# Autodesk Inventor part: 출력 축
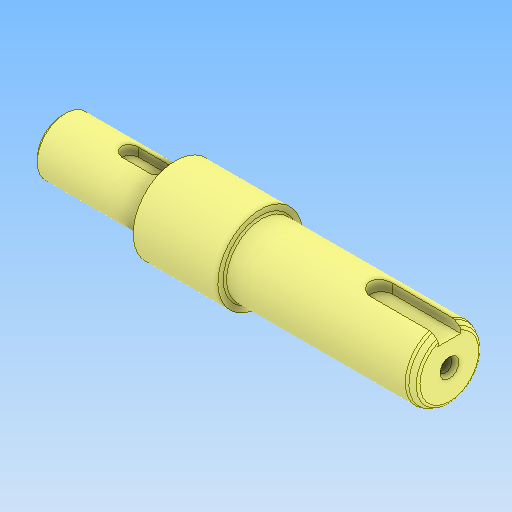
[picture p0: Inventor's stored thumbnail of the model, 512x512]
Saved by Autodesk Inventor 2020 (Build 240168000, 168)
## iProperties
Created: 2025-11
Part Number: 출력 축
Material: 강철, 탄소
Document SubType Name: Modeling
Designer: PC2-06
Density: 7.85 g/cm^3
Appearance: 기본값
Author: jhkim
Sending System: Autodesk Inventor 2026
Preprocessor: ST-DEVELOPER v20.1
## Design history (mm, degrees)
feature "솔리드1"
node "솔리드2"
